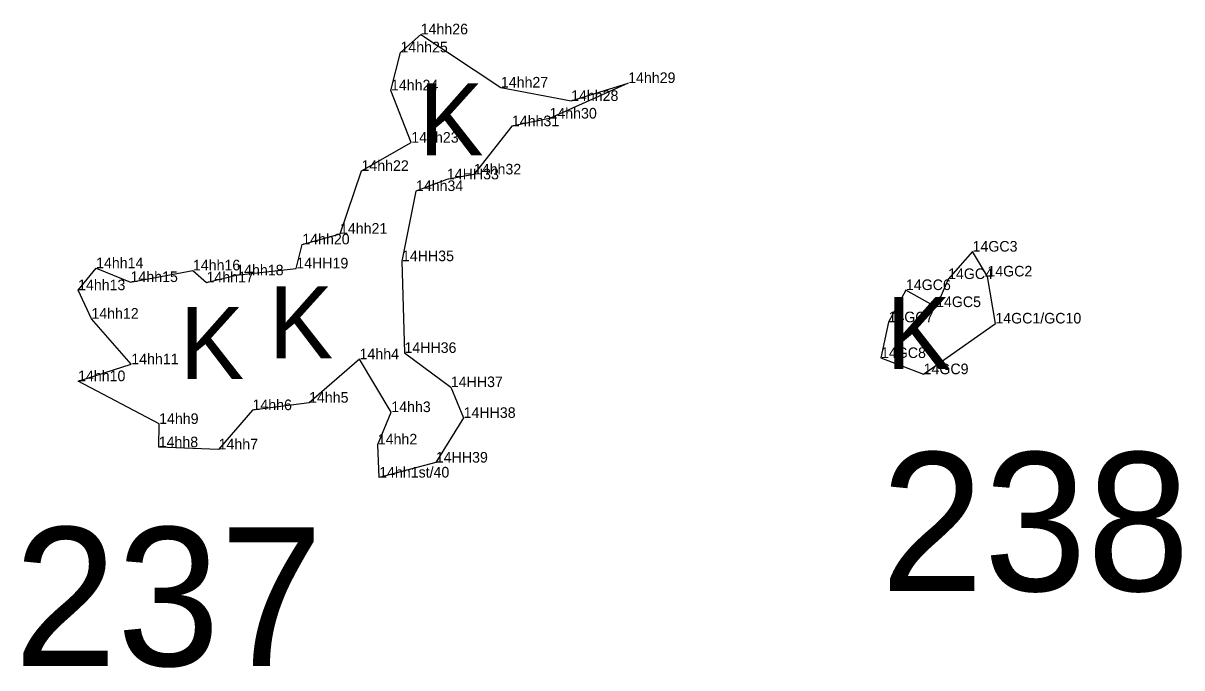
# Model space of a CAD drawing. Extents: x 2072529 to 2268812, y 436423 to 470008.
# Drawn here: x 2258156 to 2258702, y 441493 to 441797 of the extents above; entities that cross this region are included whole.
import ezdxf

# ---------------------------------------------------------------- set-up
doc = ezdxf.new("R2010")
doc.units = 0
for name, color, linetype in [('Old_Level_20', 7, 'Continuous'), ('Old_Level_52', 7, 'Continuous'), ('Old_Level_55', 7, 'Continuous'), ('Old_Level_60', 7, 'Continuous'), ('Old_Level_62', 7, 'Continuous')]:
    doc.layers.add(name, color=color, linetype=linetype)

msp = doc.modelspace()

# ---------------------------------------------------------------- linework, layer by layer
at = {"layer": 'Old_Level_20'}
for p, q in [((2258343.399, 441791.6), (2258343.399, 441791.6)), ((2258333.868, 441783.101), (2258333.868, 441783.101)), ((2258329.379, 441765.18), (2258329.379, 441765.18)), ((2258381.22, 441766.513), (2258381.22, 441766.513)), ((2258441.227, 441768.649), (2258441.227, 441768.649)), ((2258414.318, 441760.176), (2258414.318, 441760.176)), ((2258386.413, 441748.285), (2258386.413, 441748.285)), ((2258404.135, 441751.895), (2258404.135, 441751.895)), ((2258338.974, 441740.52), (2258338.974, 441740.52)), ((2258315.478, 441727.206), (2258315.478, 441727.206)), ((2258368.48, 441725.526), (2258368.48, 441725.526)), ((2258355.761, 441723.218), (2258355.761, 441723.218)), ((2258341.151, 441717.707), (2258341.151, 441717.707)), ((2258305.355, 441697.59), (2258305.355, 441697.59)), ((2258287.581, 441692.559), (2258287.581, 441692.559)), ((2258603.652, 441689.144), (2258603.652, 441689.144)), ((2258334.561, 441684.629), (2258334.561, 441684.629)), ((2258190.326, 441681.312), (2258190.326, 441681.312)), ((2258235.988, 441680.283), (2258235.988, 441680.283)), ((2258256.416, 441677.958), (2258256.416, 441677.958)), ((2258284.738, 441681.219), (2258284.738, 441681.219)), ((2258610.626, 441677.419), (2258610.626, 441677.419)), ((2258181.837, 441670.951), (2258181.837, 441670.951)), ((2258206.577, 441674.788), (2258206.577, 441674.788)), ((2258242.401, 441674.641), (2258242.401, 441674.641)), ((2258572.219, 441671.006), (2258572.219, 441671.006)), ((2258592.094, 441676.209), (2258592.094, 441676.209)), ((2258586.438, 441662.974), (2258586.438, 441662.974)), ((2258188.101, 441657.498), (2258188.101, 441657.498)), ((2258564.008, 441655.804), (2258564.008, 441655.804)), ((2258614.395, 441655.245), (2258614.395, 441655.245)), ((2258314.568, 441638.377), (2258314.568, 441638.377)), ((2258335.731, 441641.36), (2258335.731, 441641.36)), ((2258560.467, 441638.968), (2258560.467, 441638.968)), ((2258206.923, 441636.001), (2258206.923, 441636.001)), ((2258181.829, 441628.035), (2258181.829, 441628.035)), ((2258580.564, 441631.325), (2258580.564, 441631.325)), ((2258357.618, 441625.237), (2258357.618, 441625.237)), ((2258290.761, 441617.899), (2258290.761, 441617.899)), ((2258264.08, 441614.376), (2258264.08, 441614.376)), ((2258329.538, 441613.456), (2258329.538, 441613.456)), ((2258363.636, 441610.724), (2258363.636, 441610.724)), ((2258220.055, 441607.879), (2258220.055, 441607.879)), ((2258219.858, 441596.875), (2258219.858, 441596.875)), ((2258248.102, 441595.855), (2258248.102, 441595.855)), ((2258323.171, 441598.207), (2258323.171, 441598.207)), ((2258350.545, 441589.643), (2258350.545, 441589.643)), ((2258323.813, 441582.6), (2258323.813, 441582.6))]:
    msp.add_line(p, q, dxfattribs=at)
at = {"layer": 'Old_Level_52'}
for points in [[(2258323.813, 441582.6), (2258323.171, 441598.207), (2258329.538, 441613.456), (2258314.568, 441638.377), (2258290.761, 441617.899), (2258264.08, 441614.376), (2258248.102, 441595.855), (2258219.858, 441596.875), (2258220.055, 441607.879), (2258181.829, 441628.035), (2258206.923, 441636.001), (2258188.101, 441657.498), (2258181.837, 441670.951), (2258190.326, 441681.312), (2258206.577, 441674.788), (2258235.988, 441680.283), (2258242.401, 441674.641), (2258256.416, 441677.958), (2258284.738, 441681.219), (2258287.581, 441692.559), (2258305.355, 441697.59), (2258315.478, 441727.206), (2258338.974, 441740.52), (2258329.379, 441765.18), (2258333.868, 441783.101), (2258343.399, 441791.6), (2258381.22, 441766.513), (2258414.318, 441760.176), (2258441.227, 441768.649), (2258404.135, 441751.895), (2258386.413, 441748.285), (2258368.48, 441725.526), (2258355.761, 441723.218), (2258341.151, 441717.707), (2258334.561, 441684.629), (2258335.731, 441641.36), (2258357.618, 441625.237), (2258363.636, 441610.724), (2258350.545, 441589.643)], [(2258614.395, 441655.245), (2258610.626, 441677.419), (2258603.652, 441689.144), (2258592.094, 441676.209), (2258586.438, 441662.974), (2258572.219, 441671.006), (2258564.008, 441655.804), (2258560.467, 441638.968), (2258580.564, 441631.325)]]:
    msp.add_lwpolyline(points, close=True, dxfattribs=at)

# ---------------------------------------------------------------- texts
at = {"layer": 'Old_Level_55'}
for p in [(2258342.706, 441734.553), (2258271.817, 441638.802), (2258563.099, 441633.763), (2258229.821, 441629.059)]:
    msp.add_text('K', height=34, dxfattribs=at).set_placement(p)
at = {"layer": 'Old_Level_60'}
for s, p in [('14hh26', (2258343.399, 441791.6)), ('14hh25', (2258333.868, 441783.101)), ('14hh24', (2258329.379, 441765.18)), ('14hh27', (2258381.22, 441766.513)), ('14hh29', (2258441.227, 441768.649)), ('14hh28', (2258414.318, 441760.176)), ('14hh31', (2258386.413, 441748.285)), ('14hh30', (2258404.135, 441751.895)), ('14hh23', (2258338.974, 441740.52)), ('14hh22', (2258315.478, 441727.206)), ('14HH33', (2258355.761, 441723.218)), ('14hh32', (2258368.48, 441725.526)), ('14hh34', (2258341.151, 441717.707)), ('14hh21', (2258305.355, 441697.59)), ('14hh20', (2258287.581, 441692.559)), ('14GC3', (2258603.652, 441689.144)), ('14HH35', (2258334.561, 441684.629)), ('14hh14', (2258190.326, 441681.312)), ('14hh16', (2258235.988, 441680.283)), ('14hh18', (2258256.416, 441677.958)), ('14HH19', (2258284.738, 441681.219)), ('14GC2', (2258610.626, 441677.419)), ('14hh15', (2258206.577, 441674.788)), ('14hh17', (2258242.401, 441674.641)), ('14GC4', (2258592.094, 441676.209)), ('14hh13', (2258181.837, 441670.951)), ('14GC6', (2258572.219, 441671.006)), ('14GC5', (2258586.438, 441662.974)), ('14hh12', (2258188.101, 441657.498)), ('14GC7', (2258564.008, 441655.804)), ('14GC1/GC10', (2258614.395, 441655.245)), ('14hh4', (2258314.568, 441638.377)), ('14HH36', (2258335.731, 441641.36)), ('14GC8', (2258560.467, 441638.968)), ('14hh11', (2258206.923, 441636.001)), ('14hh10', (2258181.829, 441628.035)), ('14GC9', (2258580.564, 441631.325)), ('14HH37', (2258357.618, 441625.237)), ('14hh5', (2258290.761, 441617.899)), ('14hh6', (2258264.08, 441614.376)), ('14hh3', (2258329.538, 441613.456)), ('14hh9', (2258220.055, 441607.879)), ('14HH38', (2258363.636, 441610.724)), ('14hh8', (2258219.858, 441596.875)), ('14hh7', (2258248.102, 441595.855)), ('14hh2', (2258323.171, 441598.207)), ('14HH39', (2258350.545, 441589.643)), ('14hh1st/40', (2258323.813, 441582.6))]:
    msp.add_text(s, height=5, dxfattribs=at).set_placement(p)
at = {"layer": 'Old_Level_62'}
for s, p in [('238', (2258560.345, 441529.119)), ('237', (2258151.549, 441493.786))]:
    msp.add_text(s, height=65.34, dxfattribs=at).set_placement(p)

doc.saveas('drawing.dxf')
